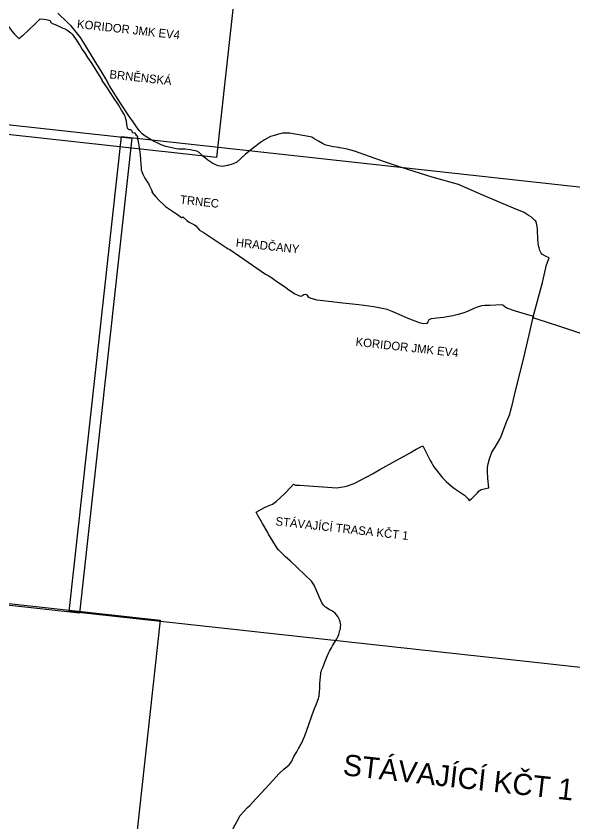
# Model space of a CAD drawing. Extents: x -678204 to -526855, y -1228851 to -1110393.
# Drawn here: x -609694 to -605756, y -1148586 to -1142888 of the extents above; entities that cross this region are included whole.
import ezdxf

# ---------------------------------------------------------------- set-up
doc = ezdxf.new("R2010")
doc.units = 0
for name, color, linetype in [('00_n_cyklo popisy detaily', 7, 'Continuous'), ('00_n_cyklo popisy_', 7, 'Continuous'), ('00_n_cyklo provereni rekreacni hlavni', 7, 'Continuous'), ('00_n_cyklo prujezdne podminecne rekreacni hlavni', 7, 'Continuous'), ('00_n_cyklo prujezdne rekreacni hlavni', 7, 'Continuous'), ('00_n_cyklo trasovani rekreacni hlavni', 7, 'Continuous'), ('_HELP', 7, 'Continuous'), ('trasy_0001', 7, 'Continuous')]:
    doc.layers.add(name, color=color, linetype=linetype)

msp = doc.modelspace()

# ---------------------------------------------------------------- linework, layer by layer
at = {"layer": '00_n_cyklo provereni rekreacni hlavni'}
for points in [[(-608732.8, -1144133.5), (-608706.2, -1144166.4), (-608681.7, -1144191.5), (-608654.4, -1144218.4), (-608636.6, -1144233.2), (-608587.9, -1144268), (-608551.4, -1144291.8), (-608523.3, -1144311)], [(-608523.3, -1144311), (-608516.2, -1144309.4), (-608513.8, -1144308.5)], [(-604907.1, -1145682.9), (-604927.4, -1145657.5), (-604966.3, -1145606.9), (-605016.2, -1145539.9), (-605094.8, -1145430.3), (-605140.2, -1145371.4), (-605188.2, -1145328.5), (-605222.4, -1145302.4), (-605272.6, -1145276), (-605322.8, -1145256.7), (-605403.7, -1145232.5), (-605474.5, -1145210.3), (-605527, -1145191.9), (-605588.2, -1145167.1), (-605680, -1145139.4), (-605743.4, -1145117.2), (-605849.7, -1145083.1), (-606009.1, -1145031.8), (-606024.1, -1145027.1)]]:
    msp.add_lwpolyline(points, dxfattribs=at)
at = {"layer": '00_n_cyklo prujezdne podminecne rekreacni hlavni'}
for points in [[(-609211.3, -1143141.7), (-609187.8, -1143181.6), (-609165.8, -1143214.5)], [(-609165.8, -1143214.5), (-609101.2, -1143314.6), (-609084, -1143342.3)], [(-608895.5, -1143689.1), (-608899.8, -1143688.6), (-608903.2, -1143685.9), (-608905.6, -1143680.4), (-608909.4, -1143666.1), (-608911.1, -1143654.9), (-608913.9, -1143628.6), (-608915.1, -1143621.2), (-608916.6, -1143614.4), (-608923.1, -1143596.1), (-608927.1, -1143587.1), (-608947.8, -1143553), (-608970.4, -1143516), (-609006, -1143463.4), (-609047.7, -1143397.6), (-609084, -1143342.3)], [(-608895.5, -1143689.1), (-608885.2, -1143690.4), (-608880.3, -1143694.1), (-608876.1, -1143699.7), (-608872, -1143706.7), (-608870.8, -1143714.3)], [(-608833.7, -1143738.6), (-608835.8, -1143737.8), (-608838.4, -1143736), (-608840.8, -1143733.6), (-608846.3, -1143721.8), (-608851.8, -1143716.5), (-608856.2, -1143714.8), (-608870.8, -1143714.3)], [(-608513.8, -1144308.5), (-608485.6, -1144334.3), (-608470.3, -1144345.8), (-608456.6, -1144353.2), (-608441.5, -1144358.9), (-608432.4, -1144363.3), (-608423.2, -1144371.7), (-608407.1, -1144388.9), (-608395.8, -1144400.6), (-608364.6, -1144421.7), (-608244.2, -1144500.3), (-608195.1, -1144533.1), (-608186.9, -1144536.4), (-608183.4, -1144538.2), (-608113.5, -1144585.4)], [(-608113.5, -1144585.4), (-607960.6, -1144691.4), (-607929.6, -1144712.3), (-607906.5, -1144724.7), (-607896, -1144731), (-607888.5, -1144735.7), (-607867.8, -1144751.1), (-607855.9, -1144759.9), (-607802.1, -1144795), (-607786.1, -1144807), (-607765.3, -1144823), (-607732.4, -1144845.3), (-607722.4, -1144851.6), (-607710.8, -1144856.4), (-607689.1, -1144867.2), (-607679.6, -1144868.8), (-607673.5, -1144867.2), (-607658.2, -1144857.2), (-607650.5, -1144855), (-607641.5, -1144856.1), (-607635.2, -1144859), (-607633.3, -1144862.4), (-607630.4, -1144877.8)]]:
    msp.add_lwpolyline(points, dxfattribs=at)
at = {"layer": '00_n_cyklo prujezdne rekreacni hlavni'}
msp.add_line((-609214, -1143141.3), (-609211.3, -1143141.7), dxfattribs=at)
for points in [[(-609839.4, -1142885.2), (-609835.7, -1142894), (-609831, -1142898.2), (-609797.3, -1142911.1), (-609788.1, -1142914.9), (-609783.5, -1142917.6), (-609778.6, -1142922.7), (-609746.3, -1142961.5), (-609739.4, -1142970), (-609733.5, -1142980.5), (-609729.3, -1142988.2), (-609720.9, -1142997.9), (-609704.6, -1143015.9), (-609677.3, -1143044.8), (-609674.6, -1143046.4), (-609671.7, -1143046.6)], [(-609523.9, -1142907.9), (-609559.5, -1142943.1), (-609649.6, -1143027.8), (-609659.4, -1143037.4), (-609667.8, -1143044.7), (-609671.7, -1143046.6)], [(-609523.9, -1142907.9), (-609498, -1142909.3), (-609480.8, -1142911.8), (-609463.4, -1142915.9), (-609453.1, -1142918.2), (-609450.3, -1142928.1), (-609447.7, -1142932.4), (-609444, -1142936.5), (-609438.3, -1142940.2), (-609430.2, -1142943.7), (-609390.9, -1142959.6), (-609362.2, -1142972.7), (-609347.9, -1142978.9)], [(-609347.9, -1142978.9), (-609342.3, -1142981.7), (-609335.7, -1142985.2), (-609324.4, -1142992.5), (-609315.7, -1142998.7), (-609307.2, -1143006), (-609298.1, -1143016.5), (-609291.3, -1143025), (-609285.6, -1143032.3), (-609267.3, -1143058.6), (-609247.2, -1143088.8), (-609241.4, -1143097.6), (-609237.6, -1143103.6), (-609225.6, -1143123.6), (-609214, -1143141.3)], [(-608833.7, -1143738.6), (-608834.8, -1143742.6), (-608835.1, -1143744.8), (-608835.1, -1143748.3), (-608834.7, -1143754.9), (-608833.6, -1143762.1), (-608828.4, -1143789.3), (-608826.1, -1143802.3), (-608823.1, -1143820.2), (-608821.9, -1143828.6), (-608819.4, -1143851.5), (-608816.9, -1143871.5), (-608814.3, -1143896.1), (-608813.1, -1143911.1), (-608812.1, -1143929.7), (-608810.3, -1143964.4), (-608810.2, -1143969.1), (-608809.5, -1143972.7), (-608808.3, -1143977.1), (-608805.3, -1143986.1), (-608802.4, -1143994), (-608797.8, -1144005), (-608791.1, -1144019.4), (-608788.1, -1144025.1), (-608785.4, -1144030.4), (-608783, -1144034.3), (-608778, -1144042), (-608765.9, -1144060.1), (-608758, -1144072.4), (-608752.3, -1144082.4), (-608744.7, -1144098.7), (-608738.2, -1144111.2), (-608735.9, -1144116.3), (-608733, -1144123.9), (-608732.1, -1144126.7), (-608731.9, -1144129.6), (-608732.1, -1144131.6), (-608732.8, -1144133.5)], [(-606024.1, -1145027.1), (-606034.5, -1145023.8), (-606033.1, -1145012.3), (-606066.9, -1145002), (-606161.6, -1144973.7), (-606224, -1144953.7), (-606236.6, -1144943.7), (-606244.6, -1144933.4), (-606259.5, -1144929.6), (-606301, -1144932.5), (-606343.8, -1144935), (-606378.6, -1144934.1), (-606402.4, -1144937.3), (-606432.1, -1144946.3), (-606456.5, -1144956), (-606501, -1144977.6), (-606528, -1144987.2), (-606567.7, -1144997.9), (-606605.3, -1145006.9), (-606671, -1145020.1), (-606719.3, -1145024.9), (-606758.9, -1145029.4), (-606774.4, -1145036.8), (-606781.8, -1145049.4), (-606789.9, -1145062.6), (-606813, -1145063.9), (-606840.7, -1145056.5), (-606921.3, -1145027.5), (-606984.4, -1144997.5), (-607034.3, -1144976.6), (-607070.4, -1144963.7), (-607164.1, -1144943.4), (-607270.3, -1144929.2), (-607382.7, -1144918), (-607563.7, -1144897.3), (-607606.6, -1144884.1), (-607622.3, -1144878.7), (-607634.5, -1144864.2)]]:
    msp.add_lwpolyline(points, dxfattribs=at)
at = {"layer": '00_n_cyklo trasovani rekreacni hlavni'}
msp.add_line((-609214, -1143141.3), (-609211.3, -1143141.7), dxfattribs=at)
for points in [[(-609839.4, -1142885.2), (-609835.7, -1142894), (-609831, -1142898.2), (-609797.3, -1142911.1), (-609788.1, -1142914.9), (-609783.5, -1142917.6), (-609778.6, -1142922.7), (-609746.3, -1142961.5), (-609739.4, -1142970), (-609733.5, -1142980.5), (-609729.3, -1142988.2), (-609720.9, -1142997.9), (-609704.6, -1143015.9), (-609677.3, -1143044.8), (-609674.6, -1143046.4), (-609671.7, -1143046.6)], [(-609523.9, -1142907.9), (-609559.5, -1142943.1), (-609649.6, -1143027.8), (-609659.4, -1143037.4), (-609667.8, -1143044.7), (-609671.7, -1143046.6)], [(-609523.9, -1142907.9), (-609498, -1142909.3), (-609480.8, -1142911.8), (-609463.4, -1142915.9), (-609453.1, -1142918.2), (-609450.3, -1142928.1), (-609447.7, -1142932.4), (-609444, -1142936.5), (-609438.3, -1142940.2), (-609430.2, -1142943.7), (-609390.9, -1142959.6), (-609362.2, -1142972.7), (-609347.9, -1142978.9)], [(-609347.9, -1142978.9), (-609342.3, -1142981.7), (-609335.7, -1142985.2), (-609324.4, -1142992.5), (-609315.7, -1142998.7), (-609307.2, -1143006), (-609298.1, -1143016.5), (-609291.3, -1143025), (-609285.6, -1143032.3), (-609267.3, -1143058.6), (-609247.2, -1143088.8), (-609241.4, -1143097.6), (-609237.6, -1143103.6), (-609225.6, -1143123.6), (-609214, -1143141.3)], [(-609211.3, -1143141.7), (-609187.8, -1143181.6), (-609165.8, -1143214.5)], [(-609165.8, -1143214.5), (-609101.2, -1143314.6), (-609084, -1143342.3)], [(-608895.5, -1143689.1), (-608899.8, -1143688.6), (-608903.2, -1143685.9), (-608905.6, -1143680.4), (-608909.4, -1143666.1), (-608911.1, -1143654.9), (-608913.9, -1143628.6), (-608915.1, -1143621.2), (-608916.6, -1143614.4), (-608923.1, -1143596.1), (-608927.1, -1143587.1), (-608947.8, -1143553), (-608970.4, -1143516), (-609006, -1143463.4), (-609047.7, -1143397.6), (-609084, -1143342.3)], [(-608895.5, -1143689.1), (-608885.2, -1143690.4), (-608880.3, -1143694.1), (-608876.1, -1143699.7), (-608872, -1143706.7), (-608870.8, -1143714.3)], [(-608833.7, -1143738.6), (-608835.8, -1143737.8), (-608838.4, -1143736), (-608840.8, -1143733.6), (-608846.3, -1143721.8), (-608851.8, -1143716.5), (-608856.2, -1143714.8), (-608870.8, -1143714.3)], [(-608833.7, -1143738.6), (-608834.8, -1143742.6), (-608835.1, -1143744.8), (-608835.1, -1143748.3), (-608834.7, -1143754.9), (-608833.6, -1143762.1), (-608828.4, -1143789.3), (-608826.1, -1143802.3), (-608823.1, -1143820.2), (-608821.9, -1143828.6), (-608819.4, -1143851.5), (-608816.9, -1143871.5), (-608814.3, -1143896.1), (-608813.1, -1143911.1), (-608812.1, -1143929.7), (-608810.3, -1143964.4), (-608810.2, -1143969.1), (-608809.5, -1143972.7), (-608808.3, -1143977.1), (-608805.3, -1143986.1), (-608802.4, -1143994), (-608797.8, -1144005), (-608791.1, -1144019.4), (-608788.1, -1144025.1), (-608785.4, -1144030.4), (-608783, -1144034.3), (-608778, -1144042), (-608765.9, -1144060.1), (-608758, -1144072.4), (-608752.3, -1144082.4), (-608744.7, -1144098.7), (-608738.2, -1144111.2), (-608735.9, -1144116.3), (-608733, -1144123.9), (-608732.1, -1144126.7), (-608731.9, -1144129.6), (-608732.1, -1144131.6), (-608732.8, -1144133.5)], [(-608732.8, -1144133.5), (-608706.2, -1144166.4), (-608681.7, -1144191.5), (-608654.4, -1144218.4), (-608636.6, -1144233.2), (-608587.9, -1144268), (-608551.4, -1144291.8), (-608523.3, -1144311)], [(-608523.3, -1144311), (-608516.2, -1144309.4), (-608513.8, -1144308.5)], [(-608513.8, -1144308.5), (-608485.6, -1144334.3), (-608470.3, -1144345.8), (-608456.6, -1144353.2), (-608441.5, -1144358.9), (-608432.4, -1144363.3), (-608423.2, -1144371.7), (-608407.1, -1144388.9), (-608395.8, -1144400.6), (-608364.6, -1144421.7), (-608244.2, -1144500.3), (-608195.1, -1144533.1), (-608186.9, -1144536.4), (-608183.4, -1144538.2), (-608113.5, -1144585.4)], [(-608113.5, -1144585.4), (-607960.6, -1144691.4), (-607929.6, -1144712.3), (-607906.5, -1144724.7), (-607896, -1144731), (-607888.5, -1144735.7), (-607867.8, -1144751.1), (-607855.9, -1144759.9), (-607802.1, -1144795), (-607786.1, -1144807), (-607765.3, -1144823), (-607732.4, -1144845.3), (-607722.4, -1144851.6), (-607710.8, -1144856.4), (-607689.1, -1144867.2), (-607679.6, -1144868.8), (-607673.5, -1144867.2), (-607658.2, -1144857.2), (-607650.5, -1144855), (-607641.5, -1144856.1), (-607635.2, -1144859), (-607633.3, -1144862.4), (-607630.4, -1144877.8)], [(-606024.1, -1145027.1), (-606034.5, -1145023.8), (-606033.1, -1145012.3), (-606066.9, -1145002), (-606161.6, -1144973.7), (-606224, -1144953.7), (-606236.6, -1144943.7), (-606244.6, -1144933.4), (-606259.5, -1144929.6), (-606301, -1144932.5), (-606343.8, -1144935), (-606378.6, -1144934.1), (-606402.4, -1144937.3), (-606432.1, -1144946.3), (-606456.5, -1144956), (-606501, -1144977.6), (-606528, -1144987.2), (-606567.7, -1144997.9), (-606605.3, -1145006.9), (-606671, -1145020.1), (-606719.3, -1145024.9), (-606758.9, -1145029.4), (-606774.4, -1145036.8), (-606781.8, -1145049.4), (-606789.9, -1145062.6), (-606813, -1145063.9), (-606840.7, -1145056.5), (-606921.3, -1145027.5), (-606984.4, -1144997.5), (-607034.3, -1144976.6), (-607070.4, -1144963.7), (-607164.1, -1144943.4), (-607270.3, -1144929.2), (-607382.7, -1144918), (-607563.7, -1144897.3), (-607606.6, -1144884.1), (-607622.3, -1144878.7), (-607634.5, -1144864.2)], [(-604907.1, -1145682.9), (-604927.4, -1145657.5), (-604966.3, -1145606.9), (-605016.2, -1145539.9), (-605094.8, -1145430.3), (-605140.2, -1145371.4), (-605188.2, -1145328.5), (-605222.4, -1145302.4), (-605272.6, -1145276), (-605322.8, -1145256.7), (-605403.7, -1145232.5), (-605474.5, -1145210.3), (-605527, -1145191.9), (-605588.2, -1145167.1), (-605680, -1145139.4), (-605743.4, -1145117.2), (-605849.7, -1145083.1), (-606009.1, -1145031.8), (-606024.1, -1145027.1)]]:
    msp.add_lwpolyline(points, dxfattribs=at)
at = {"layer": '_HELP'}
for points in [[(-612622, -1140011.8), (-607907.5, -1140529.5), (-608276.1, -1143887), (-612990.7, -1143369.3)], [(-613590.8, -1143233.9), (-608876.3, -1143751.6), (-609245, -1147109.1), (-613959.5, -1146591.4)], [(-608948.9, -1143740.2), (-604234.3, -1144257.9), (-604603, -1147615.4), (-609317.5, -1147097.7)], [(-613388.8, -1146642.2), (-608674.3, -1147159.9), (-609043, -1150517.4), (-613757.5, -1149999.7)]]:
    msp.add_lwpolyline(points, close=True, dxfattribs=at)
at = {"layer": 'trasy_0001'}
msp.add_lwpolyline([(-608164.2, -1148641.2), (-608108.6, -1148540.8), (-608056.7, -1148484.4), (-608040.5, -1148469.1), (-608022.5, -1148447.9), (-607900.8, -1148320.3), (-607832.6, -1148243), (-607801, -1148213), (-607763.5, -1148182.6), (-607746.2, -1148160.7), (-607729, -1148124.3), (-607709.6, -1148090.6), (-607696.8, -1148067.6), (-607687.3, -1148051.3), (-607677.1, -1148033.8), (-607670.5, -1148022.3), (-607667.8, -1148016.1), (-607665.5, -1148010.5), (-607661, -1147999.8), (-607653, -1147977.3), (-607624.8, -1147897.8), (-607602.7, -1147835.7), (-607582.6, -1147784), (-607574.9, -1147763.9), (-607565.3, -1147739.2), (-607559.8, -1147725), (-607555.7, -1147714.6), (-607553.3, -1147705.1), (-607551, -1147696.2), (-607549.6, -1147684.6), (-607548.3, -1147673.6), (-607547.4, -1147661.4), (-607546.1, -1147645.3), (-607545.7, -1147605.8), (-607543.7, -1147585.3), (-607541.1, -1147559.1), (-607539.5, -1147542.4), (-607538, -1147528), (-607534.3, -1147517.9), (-607530.8, -1147508.3), (-607525.2, -1147494), (-607518.4, -1147476.5), (-607512.2, -1147460.6), (-607498.3, -1147425), (-607484.1, -1147392.7), (-607478.2, -1147379.1), (-607470.8, -1147367), (-607463.9, -1147355.6), (-607455.4, -1147341.7), (-607441, -1147318.2), (-607432.2, -1147303.6), (-607425.8, -1147291.5), (-607418.9, -1147278.5), (-607412.5, -1147261.8), (-607407.2, -1147243.2), (-607403.9, -1147231.4), (-607400.7, -1147220.3), (-607399, -1147208.2), (-607398.4, -1147194.5), (-607400, -1147181.6), (-607402.5, -1147171.3), (-607405.7, -1147158.4), (-607408.2, -1147153.6), (-607418.4, -1147134.2), (-607438.5, -1147110.2), (-607456.6, -1147097), (-607480.7, -1147084.2), (-607505.8, -1147068.4), (-607518.1, -1147056.8), (-607530.8, -1147037.6), (-607586, -1146912.8), (-607603.7, -1146884.8), (-607753.3, -1146742.7), (-607790.2, -1146709.4), (-607838.7, -1146662.3), (-607848.1, -1146649.5), (-607908.2, -1146550.8), (-607914.6, -1146539.7), (-607951.4, -1146475.4), (-607985.6, -1146415.8), (-607995.2, -1146395.4), (-607936.1, -1146364), (-607915, -1146354.1), (-607881, -1146338.2), (-607871.8, -1146331.6), (-607852.6, -1146317.9), (-607792.9, -1146263.8), (-607750.1, -1146219.5), (-607732.3, -1146196.9), (-607717.9, -1146205.1), (-607688.8, -1146204.8), (-607458.5, -1146222.6), (-607426.4, -1146223.5), (-607369, -1146214.9), (-607349.2, -1146209.9), (-607304, -1146193.9), (-607173.9, -1146124.8), (-607122.2, -1146093.9), (-607010.7, -1146032.8), (-606901.6, -1145972.8), (-606892.3, -1145967.7), (-606865.3, -1145950.6), (-606818.6, -1145926.2), (-606815.3, -1145932.7), (-606765.2, -1146030.9), (-606753.4, -1146050.4), (-606750.7, -1146054.9), (-606738.7, -1146074.7), (-606720.7, -1146099.8), (-606678.3, -1146152.1), (-606652.4, -1146178.9), (-606615.6, -1146211.5), (-606592.4, -1146229.2), (-606522.6, -1146276.2), (-606497.5, -1146301.2), (-606489.3, -1146314.4), (-606470.8, -1146298.1), (-606452.2, -1146280.6), (-606432.4, -1146262), (-606420.1, -1146245.4), (-606404.3, -1146234.9), (-606350.2, -1146224.1), (-606358, -1146158.9), (-606360.4, -1146106.3), (-606359.1, -1146080.1), (-606355.2, -1146054.8), (-606345.5, -1146019.1), (-606328.8, -1145972.3), (-606306.8, -1145935.8), (-606272.3, -1145878.6), (-606262.9, -1145859), (-606222.6, -1145751.9), (-606203.2, -1145701.8), (-606198.6, -1145680.9), (-606191.4, -1145654.6), (-606186.5, -1145640.4), (-606184.2, -1145630.9), (-606168.9, -1145567.9), (-606097.8, -1145283.7), (-606058.5, -1145111.8), (-606038.9, -1145026.2), (-606036.3, -1145015), (-605972.2, -1144771), (-605942.2, -1144647.2), (-605922.9, -1144596.3), (-605945.6, -1144586.9), (-605975.6, -1144570.5), (-605980.1, -1144565.5), (-605989.1, -1144545.2), (-605995.8, -1144527.5), (-605999.2, -1144513.5), (-606003, -1144492.1), (-606005.1, -1144466.4), (-606007.4, -1144400.4), (-606007.6, -1144394.5), (-606008.3, -1144375.6), (-606012.9, -1144351.4), (-606019, -1144337.9), (-606025.2, -1144332.2), (-606049.2, -1144310.4), (-606065.2, -1144300), (-606100.2, -1144277.5), (-606129.6, -1144265.4), (-606159.5, -1144253.2), (-606266.9, -1144209.4), (-606409.8, -1144147.2), (-606565.4, -1144079.5), (-606752.5, -1144025.9), (-606968.8, -1143957.5), (-607089, -1143918.4), (-607300.8, -1143842.7), (-607352.6, -1143828.2), (-607376.3, -1143823.8), (-607405.5, -1143818.4), (-607412.4, -1143817.6), (-607448.6, -1143813.1), (-607502.4, -1143800.6), (-607527.7, -1143788.6), (-607555.9, -1143772.4), (-607589, -1143752.4), (-607603.1, -1143744.6), (-607625.6, -1143739.8), (-607760.9, -1143716.4), (-607809, -1143716), (-607820.3, -1143717.2), (-607829.6, -1143719.9), (-607844.8, -1143724.5), (-607860.1, -1143728.8), (-607894.7, -1143738.5), (-607938, -1143763.9), (-607964.3, -1143780.8), (-608014.6, -1143818.6), (-608071.8, -1143863.1), (-608104.7, -1143895.2), (-608131.9, -1143920.8), (-608147.6, -1143928), (-608164.9, -1143935.2), (-608197.2, -1143944.6), (-608201.9, -1143945.5), (-608231.4, -1143950.9), (-608249.6, -1143950.1), (-608265.3, -1143947), (-608302.1, -1143929.7), (-608337.6, -1143907.7), (-608354.6, -1143892.9), (-608372.3, -1143877.5), (-608399.6, -1143852.8), (-608415.7, -1143844.1), (-608438.7, -1143837.5), (-608463.9, -1143834.1), (-608497.3, -1143828.4), (-608545.9, -1143828.1), (-608560.6, -1143827.5), (-608634.7, -1143810.4), (-608668, -1143797.7), (-608691.3, -1143786.8), (-608726.1, -1143770.1), (-608780.4, -1143737.2), (-608802, -1143719.3), (-608822.7, -1143696.4), (-608842.7, -1143671.1), (-608866, -1143635), (-608895.7, -1143593.4), (-608956.4, -1143503), (-608988.3, -1143451.8), (-609012.3, -1143414.5), (-609032.7, -1143381), (-609060.3, -1143332), (-609093.8, -1143273.4), (-609133.8, -1143208.6), (-609203.8, -1143096.8), (-609239, -1143039.2), (-609305.2, -1142956.4), (-609330, -1142932.1), (-609399.4, -1142866)], dxfattribs=at)

# ---------------------------------------------------------------- texts
at = {"layer": '00_n_cyklo popisy detaily'}
for s, p in [('KORIDOR JMK EV4', (-609265.3, -1142971.9)), ('BRNĚNSKÁ', (-609036.1, -1143328)), ('TRNEC', (-608537.2, -1144213.6)), ('HRADČANY', (-608142.2, -1144517.5)), ('KORIDOR JMK EV4', (-607295.2, -1145219.4)), ('STÁVAJÍCÍ TRASA KČT 1', (-607861.6, -1146488.6))]:
    msp.add_text(s, height=60, rotation=353.6836, dxfattribs=at).set_placement(p)
at = {"layer": '00_n_cyklo popisy_'}
msp.add_text('STÁVAJÍCÍ KČT 1', height=150, rotation=353.6836, dxfattribs=at).set_placement((-607387.3, -1148255.2))

doc.saveas('drawing.dxf')
